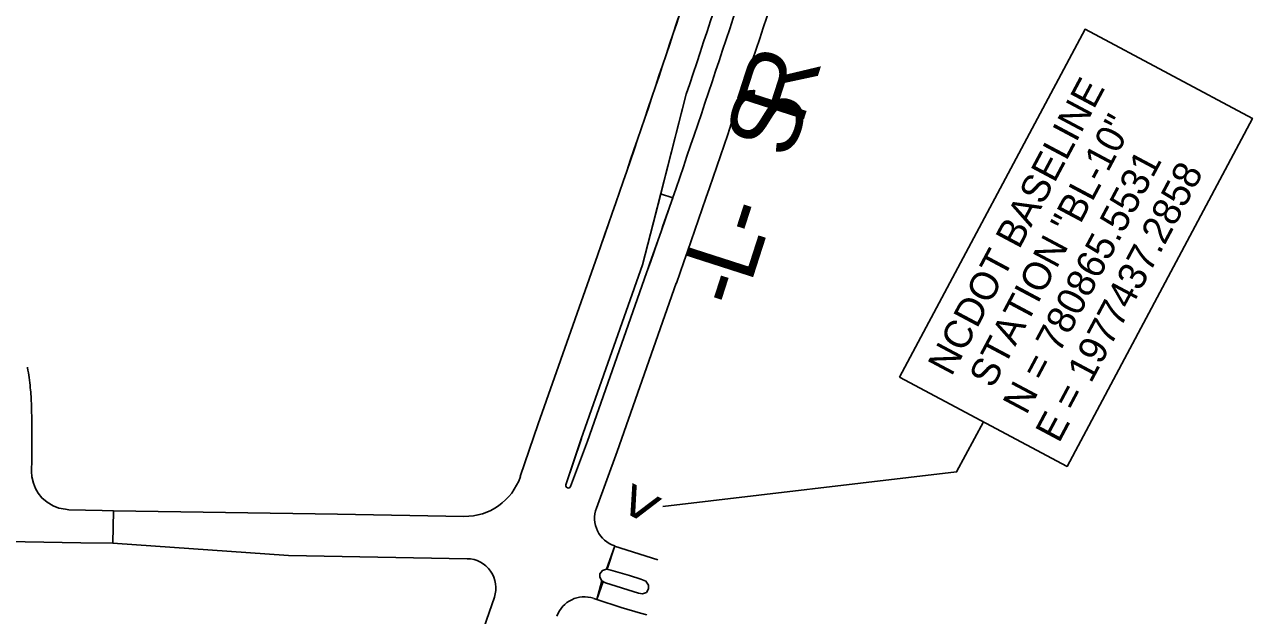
# Model space of a CAD drawing. Extents: x 1970823 to 1988115, y 770601 to 786368.
# Drawn here: x 1976934 to 1977983, y 780780 to 781285 of the extents above; entities that cross this region are included whole.
import ezdxf

# ---------------------------------------------------------------- set-up
doc = ezdxf.new("R2010")
doc.units = 0
for name, color, linetype in [('CTL Sheet Text', 7, 'Continuous'), ('CTL Supplemental Horizontal and Vertical Text', 7, 'Continuous'), ('Default', 7, 'Continuous'), ('Old_Level_3', 7, 'Continuous'), ('Old_Level_57', 7, 'Continuous')]:
    doc.layers.add(name, color=color, linetype=linetype)

msp = doc.modelspace()

# ---------------------------------------------------------------- linework, layer by layer
at = {"layer": 'CTL Supplemental Horizontal and Vertical Text'}
msp.add_lwpolyline([(1977753.1, 780945.5), (1977730.3, 780902.7), (1977479.3, 780873.2)], dxfattribs=at)
at = {"layer": 'Default'}
for p, q in [((1977499.3, 781225.4), (1977461.9, 781079.7)), ((1977372.8, 780943.8), (1977423.4, 781087.7)), ((1977409.6, 780930.9), (1977461.9, 781079.7)), ((1977414.8, 780929), (1977465.4, 781072.9)), ((1977440.2, 780920.1), (1977490.8, 781064)), ((1977357.5, 780898.6), (1977372.8, 780943.8)), ((1977396.5, 780891.5), (1977409.7, 780931.1)), ((1977400.3, 780890.2), (1977414.8, 780929)), ((1977422.6, 780871.7), (1977440.2, 780920.1)), ((1977010, 780869.5), (1977009.5, 780841.8)), ((1977010, 780869.5), (1977201.4, 780866.4)), ((1977201.4, 780866.4), (1977309.3, 780864.6)), ((1977009.5, 780841.8), (1977159.6, 780831.1)), ((1977159.6, 780831.1), (1977312.1, 780828.5)), ((1977431.6, 780819.4), (1977438.2, 780839.4)), ((1977425.4, 780812.7), (1977425.6, 780815.6)), ((1977427.3, 780809.6), (1977425.4, 780812.7)), ((1977425.6, 780815.6), (1977427.6, 780818.3)), ((1977428.2, 780809.1), (1977427.3, 780809.6)), ((1977427.6, 780818.3), (1977431.1, 780819.5)), ((1977431.1, 780819.5), (1977431.6, 780819.4)), ((1977423, 780793.7), (1977428.2, 780809.1)), ((1977326.5, 780769.3), (1977335.4, 780795.5)), ((1977423, 780793.7), (1977420.2, 780794.6))]:
    msp.add_line(p, q, dxfattribs=at)
msp.add_lwpolyline([(1977681.6, 780983.6), (1977840, 781280.9), (1977983, 781204.7), (1977824.6, 780907.4)], close=True, dxfattribs=at)
for points in [[(1977396.5, 780891.5), (1977409.6, 780930.9), (1977461.9, 781079.7), (1977477.5, 781140.3), (1977499.3, 781225.4)], [(1977487.6, 781136.9), (1977486.9, 781137.1), (1977478.2, 781140.1), (1977477.5, 781140.4), (1977461.9, 781079.7), (1977409.6, 780930.9), (1977396.5, 780891.5)], [(1977423.4, 781087.7), (1977372.8, 780943.8), (1977357.5, 780898.6)], [(1977400.3, 780890.2), (1977414.8, 780929), (1977465.4, 781072.9)], [(1977465.4, 781072.9), (1977414.8, 780929), (1977400.3, 780890.2)], [(1977422.6, 780871.7), (1977440.2, 780920.1), (1977490.8, 781064)], [(1977309.3, 780864.6), (1977201.4, 780866.4), (1977010, 780869.5), (1977009.5, 780841.8), (1977159.6, 780831.1), (1977312.1, 780828.5)], [(1977420.2, 780794.6), (1977423, 780793.7), (1977427.3, 780809.6), (1977425.4, 780812.7), (1977425.6, 780815.6), (1977427.6, 780818.3), (1977431.1, 780819.5), (1977438.2, 780839.4)], [(1977335.4, 780795.5), (1977326.5, 780769.3), (1977287.5, 780658.4)]]:
    msp.add_lwpolyline(points, dxfattribs=at)
for centre, radius, start, end in [((1967080, 784724.8), 10964.2, 340.62647, 342.22085), ((1967080, 784724.8), 10964.3, 340.62647, 342.22085), ((1967080, 784724.8), 10991.2, 341.43473, 342.22085), ((1967080, 784724.8), 10991.2, 341.43473, 342.22085), ((1967080, 784724.8), 11008.8, 340.62647, 342.22085), ((1967080, 784724.8), 11008.8, 340.62647, 342.22085), ((1967080, 784724.8), 11035.8, 340.62647, 342.22085), ((1967080, 784724.8), 11035.8, 340.62647, 342.22085), ((1967080, 784724.8), 11008.8, 340.62647, 340.97892), ((1977310.2, 780914.6), 50, 269.0355, 341.3426), ((1977310.2, 780914.6), 50, 269.0355, 341.3426), ((1977398.4, 780890.8), 2, 160.3563, 340.9173), ((1977398.4, 780890.8), 2, 160.3563, 340.9173), ((1977398.4, 780890.8), 2, 160.3563, 340.9173), ((1977446, 780863.1), 25, 159.9103, 251.6828), ((1977446, 780863.1), 25, 159.9103, 251.6828), ((1977311.7, 780803.5), 25, 341.3426, 89.0355), ((1977311.7, 780803.5), 25, 341.3426, 89.0355), ((1977412.3, 780770.9), 25, 71.6828, 159.9103), ((1977412.3, 780770.9), 25, 71.6828, 159.9103)]:
    msp.add_arc(centre, radius, start, end, dxfattribs=at)
at = {"layer": 'Old_Level_3'}
for p, q in [((1976968.9, 780870.7), (1976971.8, 780870.3)), ((1977000.3, 780869.7), (1976971.8, 780870.2)), ((1977010, 780869.5), (1977000.3, 780869.7)), ((1976982, 780842.1), (1977009.5, 780841.8)), ((1977425.4, 780812.7), (1977425.6, 780815.6))]:
    msp.add_line(p, q, dxfattribs=at)
for points in [[(1976939.6, 780967.3), (1976940.2, 780946.9)], [(1976968.9, 780870.7), (1976963.2, 780871.7), (1976958.4, 780873.6), (1976953.2, 780876.7), (1976948.7, 780880.4), (1976945.5, 780884.5), (1976943.2, 780888.6), (1976941.5, 780892.9), (1976940.3, 780898.4), (1976940, 780903.1), (1976940.2, 780913.2), (1976940.2, 780946.6)], [(1976982, 780842.1), (1976934.6, 780842.9), (1976893.6, 780843.6), (1976852.3, 780844.2), (1976821.9, 780844.7)], [(1977438.1, 780839.3), (1977475.1, 780827.4)], [(1977425.6, 780815.6), (1977427.6, 780818.3), (1977431.1, 780819.5), (1977434.9, 780818.8), (1977450.8, 780814), (1977460.6, 780810.9), (1977464.8, 780809.2), (1977467, 780805.9), (1977467.1, 780802.6), (1977465.2, 780799.7), (1977462, 780798.5), (1977458.5, 780799.1), (1977430.4, 780807.9), (1977427.3, 780809.6), (1977425.4, 780812.7)], [(1977423, 780793.7), (1977443.8, 780786.8), (1977460.2, 780781.8), (1977465.6, 780780.5)]]:
    msp.add_lwpolyline(points, dxfattribs=at)
msp.add_spline([(1976936.4, 780992.2), (1976936.5, 780991.7), (1976938.9, 780974.6), (1976939.6, 780967.2)], degree=3, dxfattribs=at)

# ---------------------------------------------------------------- texts
at = {"layer": 'CTL Sheet Text'}
for s, p in [('R', (1977597.8, 781197.7)), ('S', (1977588.4, 781168.5)), ('-', (1977566.7, 781101)), ('L', (1977554.4, 781062.8)), ('-', (1977547.2, 781040.3))]:
    msp.add_text(s, height=60, rotation=72.1693, dxfattribs=at).set_placement(p)
at = {"layer": 'CTL Supplemental Horizontal and Vertical Text'}
for s, p in [('NCDOT BASELINE', (1977725.8, 780983.6)), ('STATION "BL-10"', (1977761, 780973.2)), ('N = 780865.5531', (1977789.8, 780950.6)), ('E = 1977437.2858', (1977817.7, 780926.5))]:
    msp.add_text(s, height=24, rotation=61.9471, dxfattribs=at).set_placement(p)
at = {"layer": 'Old_Level_57'}
msp.add_text('>', height=39.1, rotation=241.9613, dxfattribs=at).set_placement((1977450.7, 780897.5))

doc.saveas('drawing.dxf')
